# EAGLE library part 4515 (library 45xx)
4-bit latch 4-16 line DECODER
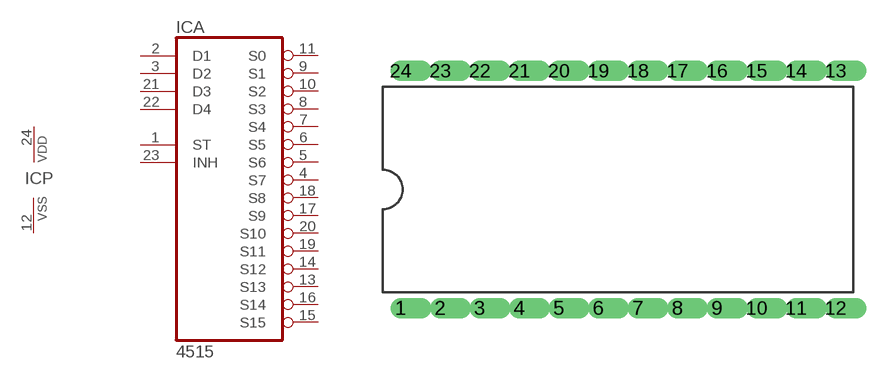
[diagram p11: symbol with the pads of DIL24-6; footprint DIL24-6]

Designator prefix IC; gates A=4515 P=PWRN

## 4515N  [DIL24-6]
1  A:ST  in
2  A:D1  in
3  A:D2  in
4  A:S7  out
5  A:S6  out
6  A:S5  out
7  A:S4  out
8  A:S3  out
9  A:S1  out
10  A:S2  out
11  A:S0  out
12  P:VSS  pwr
13  A:S13  out
14  A:S12  out
15  A:S15  out
16  A:S14  out
17  A:S9  out
18  A:S8  out
19  A:S11  out
20  A:S10  out
21  A:D3  in
22  A:D4  in
23  A:INH  in
24  P:VDD  pwr

## Footprint DIL24-6 (pad centres in mm)
Dual In Line 0.6 inch
drill 0.813 offset: 1 -13.97,-7.62; 2 -11.43,-7.62; 3 -8.89,-7.62; 4 -6.35,-7.62; 5 -3.81,-7.62; 6 -1.27,-7.62; 7 1.27,-7.62; 8 3.81,-7.62; 9 6.35,-7.62; 10 8.89,-7.62; 11 11.43,-7.62; 12 13.97,-7.62; 13 13.97,7.62; 14 11.43,7.62; 15 8.89,7.62; 16 6.35,7.62; 17 3.81,7.62; 18 1.27,7.62; 19 -1.27,7.62; 20 -3.81,7.62; 21 -6.35,7.62; 22 -8.89,7.62; 23 -11.43,7.62; 24 -13.97,7.62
